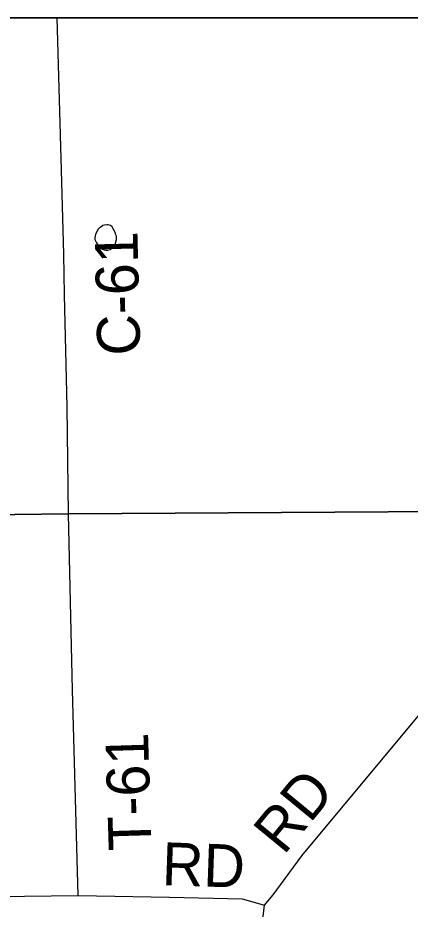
# Model space of a CAD drawing. Extents: x 0 to 34, y 0 to 22.
# Drawn here: x 4.168 to 4.688, y 19.717 to 20.9 of the extents above; entities that cross this region are included whole.
import ezdxf

# ---------------------------------------------------------------- set-up
doc = ezdxf.new("R2010")
doc.units = 0
for name, color, linetype in [('GM_X_Corporation', 7, 'Continuous'), ('GM_X_County_Road', 7, 'Continuous'), ('GM_X_County_Road_Text', 7, 'Continuous'), ('GM_X_Minor_Lake', 7, 'Continuous'), ('GM_X_Township_Road', 7, 'Continuous'), ('GM_X_Township_Road_Text', 7, 'Continuous'), ('SH_Data', 7, 'Continuous')]:
    doc.layers.add(name, color=color, linetype=linetype)

msp = doc.modelspace()

# ---------------------------------------------------------------- linework, layer by layer
at = {"layer": 'GM_X_Corporation'}
for points in [[(7.8853, 20.9), (2.1, 20.9)], [(7.8853, 20.9), (2.6713, 20.9)], [(4.9416, 20.2461), (4.2353, 20.2419), (3.8443, 20.2368)], [(3.8443, 20.2368), (4.2353, 20.2419), (4.9416, 20.2461)], [(4.9416, 20.2461), (4.2353, 20.2419), (3.8443, 20.2368)], [(3.8443, 20.2368), (4.2353, 20.2419), (4.9416, 20.2461)]]:
    msp.add_lwpolyline(points, dxfattribs=at)
at = {"layer": 'GM_X_County_Road'}
msp.add_lwpolyline([(4.2355, 20.2414), (4.2336, 20.3838), (4.2302, 20.533), (4.229, 20.5858), (4.2262, 20.6977), (4.2205, 20.9)], dxfattribs=at)
at = {"layer": 'GM_X_Minor_Lake'}
for points in [[(4.2732, 20.617), (4.2712, 20.6128), (4.2701, 20.6079), (4.2705, 20.606), (4.2713, 20.6041), (4.2725, 20.6014), (4.2744, 20.5988), (4.2759, 20.5965), (4.2779, 20.5946), (4.2805, 20.5931), (4.2828, 20.592), (4.2847, 20.5916), (4.2874, 20.5917), (4.2908, 20.5928), (4.2934, 20.5948), (4.2953, 20.5963), (4.2972, 20.5986), (4.2983, 20.6028), (4.299, 20.6059), (4.299, 20.6101), (4.2982, 20.612), (4.2978, 20.6139), (4.2963, 20.6173), (4.2943, 20.6207), (4.2932, 20.6226), (4.2909, 20.6244), (4.2882, 20.6255)], [(4.2882, 20.6255), (4.2863, 20.6255), (4.2833, 20.6247), (4.281, 20.6243), (4.2783, 20.6224), (4.2764, 20.6212), (4.2742, 20.6189), (4.2732, 20.617)]]:
    msp.add_lwpolyline(points, dxfattribs=at)
at = {"layer": 'GM_X_Township_Road'}
msp.add_line((3.817, 19.7314), (4.248, 19.7353), dxfattribs=at)
for points in [[(4.248, 19.7353), (4.2406, 20.0085), (4.2355, 20.2414)], [(4.4951, 19.7226), (4.5065, 19.7362), (4.5448, 19.7883), (4.7056, 19.9814), (4.7833, 20.0765), (4.849, 20.1455), (4.9123, 20.2121), (4.9418, 20.2456)], [(4.248, 19.7353), (4.3691, 19.7333), (4.4658, 19.7309), (4.4951, 19.7226)], [(4.5164, 18.4527), (4.5119, 18.4725), (4.498, 18.5384), (4.4783, 18.6273), (4.4577, 18.6971), (4.4306, 18.8465), (4.4032, 19.0032), (4.394, 19.0488), (4.3932, 19.0568), (4.3941, 19.0716), (4.4022, 19.116), (4.427, 19.2307), (4.4554, 19.4164), (4.4883, 19.6622), (4.4951, 19.7226)]]:
    msp.add_lwpolyline(points, dxfattribs=at)
at = {"layer": 'SH_Data'}
msp.add_line((2.1, 20.9), (8.9, 20.9), dxfattribs=at)

# ---------------------------------------------------------------- texts
at = {"layer": 'GM_X_County_Road_Text'}
msp.add_text('C-61', height=0.05682, rotation=91.3839, dxfattribs=at).set_placement((4.3307, 20.4525))
at = {"layer": 'GM_X_Township_Road_Text'}
for s, rotation, p in [('T-61', 91.7669, (4.3456, 19.7959)), ('RD', 50.5732, (4.5206, 19.7879)), ('RD', 358.0244, (4.3586, 19.7494))]:
    msp.add_text(s, height=0.05682, rotation=rotation, dxfattribs=at).set_placement(p)

doc.saveas('drawing.dxf')
